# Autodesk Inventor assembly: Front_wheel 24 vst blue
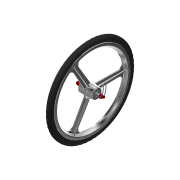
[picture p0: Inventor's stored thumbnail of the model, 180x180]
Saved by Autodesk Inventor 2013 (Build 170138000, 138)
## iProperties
Shininess: 20.0
Length Units: 11269
Angle Units: 11279
Time Units: 11290
Mass Units: 11283
Length Display Precision: 3
Angle Display Precision: 2
Created: 2001-04
Part Number: Front_wheel 24 vst blue
Document SubType Name: Baugruppe
Designer: dl
Density: 0.0
Volumn: 0.0
Area: 0.0
PropertySet Name: Model Information
Control State: 0
Master: False
Checked Out: False
Author: dl
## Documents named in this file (8)
- C:\Webworld\Webworld2014\ATC2013\Assemblies\ATC-Baby Carriage\3-FRONT WHEEL\Front_wheel 24 vst blue.iam
- C:\Webworld\Webworld2014\ATC2013\Assemblies\ATC-Baby Carriage\3-FRONT WHEEL\Quick-action_lock_nut vst.iam
- C:\Webworld\Webworld2014\ATC2013\Assemblies\ATC-Baby Carriage\3-FRONT WHEEL\Front_wheel_axis 24.ipt
- C:\Webworld\Webworld2014\ATC2013\Assemblies\ATC-Baby Carriage\3-FRONT WHEEL\Circlip - DIN 471 - 15 X 1.ipt
- C:\Webworld\Webworld2014\ATC2013\Assemblies\ATC-Baby Carriage\3-FRONT WHEEL\Rim_carbon.ipt
- C:\Webworld\Webworld2014\ATC2013\Assemblies\ATC-Baby Carriage\3-FRONT WHEEL\Tyre.ipt
- C:\Webworld\Webworld2014\ATC2013\Assemblies\ATC-Baby Carriage\3-FRONT WHEEL\DIN 625 T1 - 6201 - 12 x 32 x 10.ipt
- C:\Webworld\Webworld2014\ATC2013\Assemblies\ATC-Baby Carriage\3-FRONT WHEEL\Bearing_shell.ipt
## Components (9 placed, 7 different names)
1. Quick-action_lock_nut vst:1 [sub-assembly] — Mate:1, Mate:2
2. Front_wheel_axis 24:1 — Mate:1, Mate:2
3. Tyre:1
4. Circlip - DIN 471 - 15 X 1:1
5. Circlip - DIN 471 - 15 X 1:2
6. DIN 625 T1 - 6201 - 12 x 32 x 10:1 — Insert:1
7. DIN 625 T1 - 6201 - 12 x 32 x 10:2
8. Rim_carbon:1 — Insert:2
9. Bearing_shell:1 — Insert:1, Insert:2
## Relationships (4: Mate 2, Insert 2)
- Mate:1: Quick-action_lock_nut vst:1 ↔ Front_wheel_axis 24:1
- Mate:2: Quick-action_lock_nut vst:1 ↔ Front_wheel_axis 24:1
- Insert:1: DIN 625 T1 - 6201 - 12 x 32 x 10:1 ↔ Bearing_shell:1
- Insert:2: Rim_carbon:1 ↔ Bearing_shell:1
